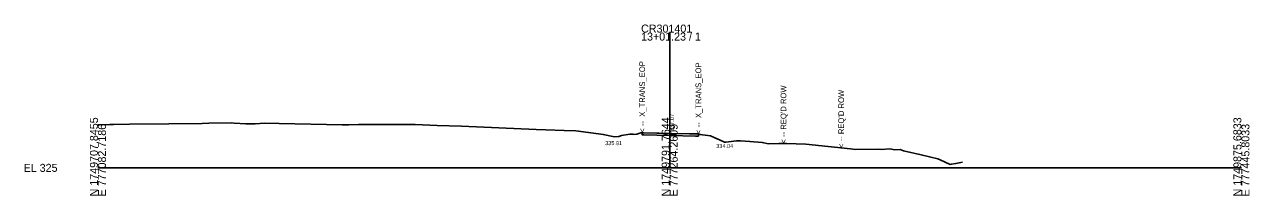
# Model space of a CAD drawing. Extents: x 765710 to 788731, y 1743078 to 1754528.
# Drawn here: x 785302.9 to 785731.5, y 1744452.4 to 1744512.3 of the extents above; entities that cross this region are included whole.
import ezdxf

# ---------------------------------------------------------------- set-up
doc = ezdxf.new("R2010")
doc.units = 0
for name, color, linetype in [('ControlPoints', 7, 'Continuous'), ('Level 1', 7, 'Continuous'), ('Observations', 7, 'Continuous'), ('Setups', 7, 'Continuous'), ('SHEET_PLOTTING_SHAPE', 7, 'Continuous'), ('SHEET_WORK_NUMBER', 7, 'Continuous'), ('TS_BACKBONE', 7, 'Continuous'), ('TS_SUBGRADE', 7, 'Continuous'), ('TS_X_GROUND', 7, 'Continuous')]:
    doc.layers.add(name, color=color, linetype=linetype)

msp = doc.modelspace()

# ---------------------------------------------------------------- linework, layer by layer
at = {"layer": 'ControlPoints'}
msp.add_lwpolyline([(785328.64, 1744477.13), (785332.8, 1744477.26), (785334.04, 1744477.27), (785339.64, 1744477.34), (785353.46, 1744477.48), (785365.13, 1744477.6), (785367.4, 1744477.69), (785375.36, 1744477.89), (785376.32, 1744477.75), (785380.37, 1744477.52), (785383.58, 1744477.51), (785386.87, 1744477.75), (785392.01, 1744477.59), (785414.05, 1744477.16), (785416.45, 1744477.16), (785419.82, 1744477.23), (785433.53, 1744477.29), (785436.6, 1744477.26), (785439.57, 1744477.32), (785447.3, 1744476.9), (785455.84, 1744476.67), (785481.88, 1744475.56), (785485.35, 1744475.39), (785491.78, 1744475.15), (785495.78, 1744475.01), (785503.73, 1744473.99), (785505.43, 1744473.8), (785509.3, 1744473.01), (785510.84, 1744473.08), (785511.79, 1744473.38), (785514.73, 1744473.92), (785515.82, 1744473.95), (785515.94, 1744473.8), (785517.15, 1744473.93), (785518.51, 1744474.32), (785519.03, 1744474.42), (785524.93, 1744474.24), (785528.64, 1744474.16), (785529.34, 1744474.14), (785535.56, 1744474.03), (785538.68, 1744473.93), (785540.15, 1744473.67), (785542.9, 1744473.27), (785544.44, 1744472.66), (785546.02, 1744471.95), (785547.84, 1744471.14), (785548.3, 1744471.14), (785552.04, 1744471.57), (785553.37, 1744471.58), (785556.7, 1744471.3), (785561.02, 1744471.01), (785563.19, 1744470.55), (785566.77, 1744470.68), (785568.49, 1744470.63), (785569.52, 1744470.58), (785576.27, 1744470.39), (785591.84, 1744468.73), (785593.48, 1744468.55), (785601.68, 1744468.6), (785602.76, 1744468.55), (785605.65, 1744468.73), (785607.38, 1744468.46), (785609.31, 1744468.49), (785610.47, 1744468.02), (785616.59, 1744466.64), (785622.47, 1744465.25), (785623.21, 1744464.92), (785626.79, 1744463.32), (785627.19, 1744463.4), (785628.72, 1744463.68), (785631.09, 1744464.12)], dxfattribs=at)
at = {"layer": 'Setups'}
for p, q in [((785528.64, 1744462.1), (785528.64, 1744509.47)), ((785328.64, 1744462.1), (785528.64, 1744462.1)), ((785528.64, 1744462.1), (785728.64, 1744462.1))]:
    msp.add_line(p, q, dxfattribs=at)
at = {"layer": 'SHEET_PLOTTING_SHAPE'}
for p, q in [((785518.99, 1744473.67), (785519.03, 1744474.42)), ((785519.6, 1744473.66), (785518.99, 1744473.67)), ((785519.6, 1744473.66), (785528.64, 1744473.43)), ((785528.64, 1744473.43), (785537.64, 1744473.25)), ((785537.64, 1744473.25), (785538.68, 1744473.23)), ((785538.68, 1744473.23), (785538.68, 1744473.98))]:
    msp.add_line(p, q, dxfattribs=at)
at = {"layer": 'SHEET_WORK_NUMBER'}
for p, q in [((785519.64, 1744474.41), (785519.03, 1744474.42)), ((785528.64, 1744474.18), (785519.64, 1744474.41)), ((785537.64, 1744474), (785528.64, 1744474.18)), ((785537.64, 1744474), (785538.68, 1744473.98)), ((785538.68, 1744473.98), (785539.28, 1744473.82))]:
    msp.add_line(p, q, dxfattribs=at)
at = {"layer": 'TS_SUBGRADE'}
for points in [[(785535.56, 1744474.03), (785538.68, 1744473.93), (785538.68, 1744473.23), (785537.64, 1744473.25), (785528.64, 1744473.43), (785519.6, 1744473.66), (785518.99, 1744473.67), (785519.03, 1744474.42), (785524.93, 1744474.24), (785528.64, 1744474.16), (785529.34, 1744474.14)], [(785538.68, 1744473.93), (785538.68, 1744473.98), (785537.64, 1744474), (785528.64, 1744474.18), (785519.64, 1744474.41), (785519.03, 1744474.42), (785524.93, 1744474.24), (785528.64, 1744474.16), (785529.34, 1744474.14), (785535.56, 1744474.03)], [(785538.68, 1744473.93), (785538.68, 1744473.98), (785539.28, 1744473.82)]]:
    msp.add_lwpolyline(points, close=True, dxfattribs=at)

# ---------------------------------------------------------------- texts
at = {"layer": 'Level 1'}
for p in [(785569.44, 1744470.63), (785589.64, 1744469.07)]:
    msp.add_text("< -- REQ'D ROW", height=2, rotation=90, dxfattribs=at).set_placement(p)
at = {"layer": 'Observations'}
for s, p in [('335.91', (785506.08, 1744470.05)), ('334.04', (785544.93, 1744469.04))]:
    msp.add_text(s, height=1.4, dxfattribs=at).set_placement(p)
at = {"layer": 'Setups'}
for s, p in [('CR301401', (785518.64, 1744509.47)), ('13+01.23 / 1', (785518.64, 1744506.67)), ('EL 325', (785302.64, 1744460.7))]:
    msp.add_text(s, height=2.8, dxfattribs=at).set_placement(p)
for s, p in [('N 1749707.8455', (785328.64, 1744452.1)), ('N 1749791.7644', (785528.64, 1744452.1)), ('N 1749875.6833', (785728.64, 1744452.1)), ('E 777082.7186', (785331.44, 1744452.1)), ('E 777264.2609', (785531.44, 1744452.1)), ('E 777445.8033', (785731.44, 1744452.1))]:
    msp.add_text(s, height=2.8, rotation=90, dxfattribs=at).set_placement(p)
at = {"layer": 'TS_BACKBONE'}
msp.add_text(' 337.07', height=1.5, rotation=90, dxfattribs=at).set_placement((785530.14, 1744474.18))
at = {"layer": 'TS_X_GROUND'}
for p in [(785520.03, 1744474.42), (785539.68, 1744473.98)]:
    msp.add_text('< --  X_TRANS_EOP', height=2, rotation=90, dxfattribs=at).set_placement(p)

doc.saveas('drawing.dxf')
